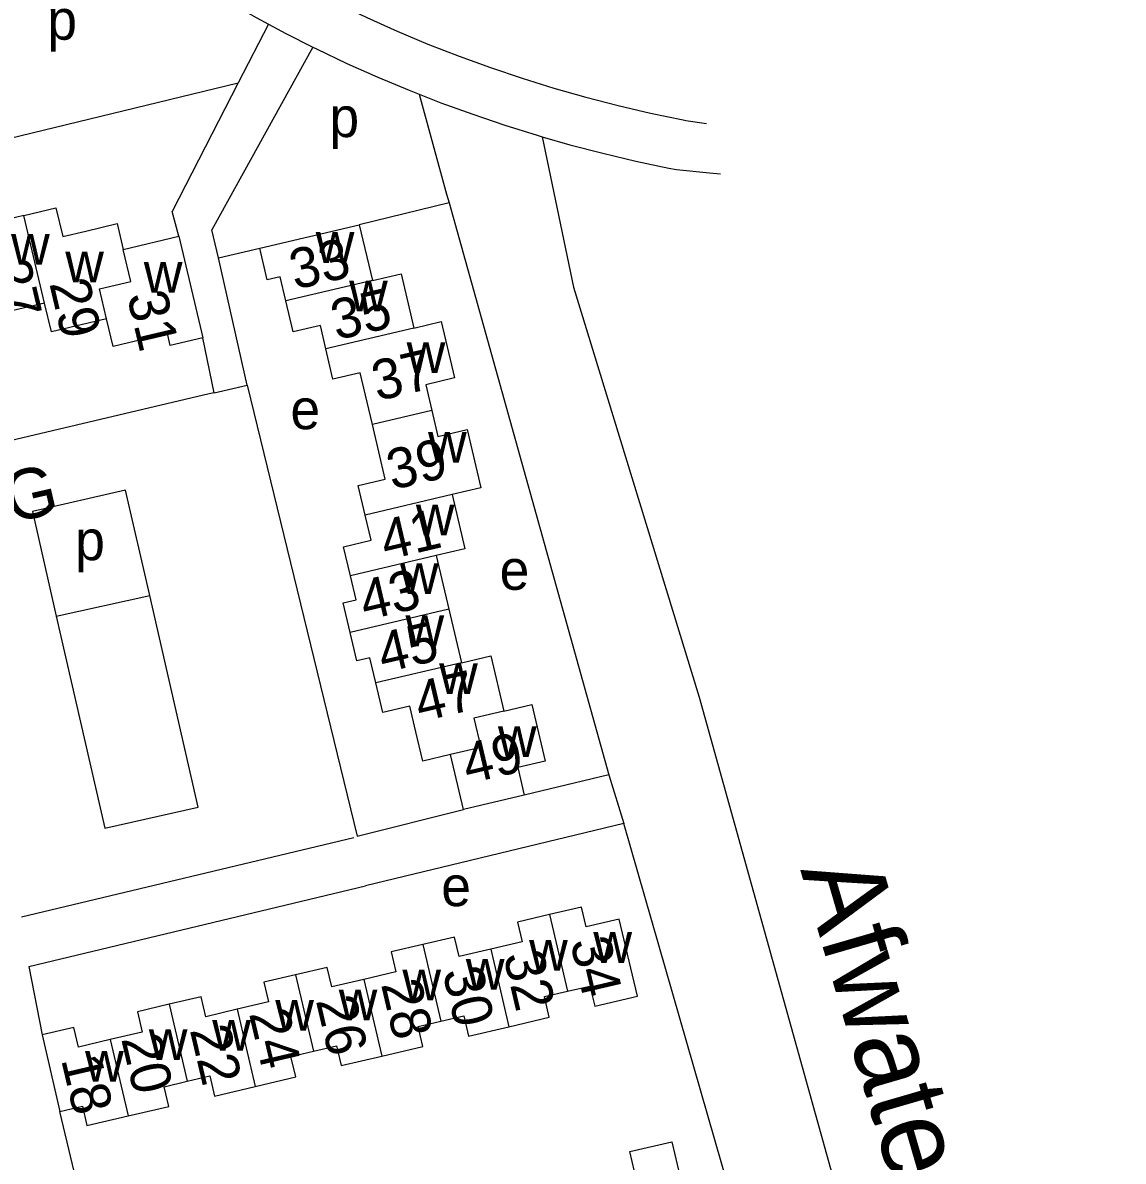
# Model space of a CAD drawing. Extents: x 157646 to 159241, y 379213 to 381217.
# Drawn here: x 159119.4 to 159229.5, y 380620.1 to 380734 of the extents above; entities that cross this region are included whole.
import ezdxf

# ---------------------------------------------------------------- set-up
doc = ezdxf.new("R2010")
doc.units = 0
for name, color, linetype in [('BLT_Basislijn', 7, 'Continuous'), ('BLT_Bebouwing', 7, 'Continuous'), ('BLT_Centroide', 7, 'Continuous'), ('BLT_Huisnummer', 7, 'Continuous'), ('BLT_Huisnummer_ tussenligend', 7, 'Continuous'), ('BLT_Onderverdeling_panden', 7, 'Continuous'), ('BLT_Straatnaam', 7, 'Continuous'), ('BLT_Waternaam_spoorwegen', 7, 'Continuous')]:
    doc.layers.add(name, color=color, linetype=linetype)

msp = doc.modelspace()

# ---------------------------------------------------------------- linework, layer by layer
at = {"layer": 'BLT_Basislijn'}
for p, q in [((159143.95, 380733.82), (159140.92, 380727.95)), ((159148.39, 380731.52), (159138.28, 380713.24)), ((159115.84, 380721.89), (159140.92, 380727.95)), ((159140.92, 380727.95), (159134.29, 380715.08)), ((159162.01, 380715.93), (159153.03, 380713.74)), ((159134.96, 380712.6), (159134.29, 380715.08)), ((159138.93, 380710.45), (159138.28, 380713.24)), ((159138.93, 380710.45), (159143.07, 380711.4)), ((159141.8, 380697.69), (159138.93, 380710.45)), ((159138.5, 380696.95), (159137.36, 380702.45)), ((159138.5, 380696.95), (159141.8, 380697.69)), ((159141.8, 380697.69), (159152.8, 380652.57)), ((159120.32, 380685.07), (159122.71, 380674.59)), ((159122.71, 380674.59), (159132.06, 380676.66)), ((159178.01, 380658.73), (159179.5, 380653.84)), ((159152.8, 380652.57), (159163.44, 380655.25)), ((159119.24, 380644.51), (159152.47, 380652.46)), ((159119.96, 380639.55), (159153.64, 380647.6)), ((159119.96, 380639.55), (159121.29, 380632.7)), ((159127.44, 380606.57), (159123.08, 380625.05))]:
    msp.add_line(p, q, dxfattribs=at)
for points in [[(159128.09, 380749.91), (159130.77, 380747.93), (159133.5, 380746.01), (159136.28, 380744.16), (159139.1, 380742.37), (159141.96, 380740.65), (159144.86, 380739), (159147.79, 380737.43), (159150.77, 380735.92), (159153.78, 380734.48), (159156.83, 380733.12), (159159.9, 380731.83), (159163.01, 380730.61), (159166.14, 380729.47), (159169.31, 380728.41), (159172.49, 380727.42), (159175.7, 380726.51), (159178.93, 380725.67), (159182.18, 380724.91), (159185.44, 380724.23), (159185.71, 380724.18)], [(159122.91, 380747.6), (159125.6, 380745.53), (159128.34, 380743.52), (159131.12, 380741.58), (159133.96, 380739.7), (159136.83, 380737.89), (159139.74, 380736.15), (159142.7, 380734.48), (159143.95, 380733.82)], [(159143.95, 380733.82), (159145.69, 380732.88), (159148.39, 380731.52)], [(159148.39, 380731.52), (159148.73, 380731.35), (159151.79, 380729.89), (159154.89, 380728.51), (159158.02, 380727.2), (159159.01, 380726.81)], [(159159.01, 380726.81), (159161.18, 380725.96), (159164.38, 380724.8), (159167.59, 380723.71), (159170.83, 380722.7), (159171.34, 380722.55)], [(159159.01, 380726.81), (159161.77, 380716.81), (159162.01, 380715.93)], [(159185.71, 380724.18), (159187.78, 380723.88)], [(159171.34, 380722.55), (159174.1, 380721.76), (159177.38, 380720.9), (159180.69, 380720.12), (159184.01, 380719.42), (159184.77, 380719.27)], [(159171.34, 380722.55), (159174.47, 380707.52), (159187.04, 380666.49), (159204.66, 380603.29)], [(159184.77, 380719.27), (159188.07, 380718.94), (159189.17, 380718.86)], [(159162.01, 380715.93), (159178.01, 380658.73)], [(159138.5, 380696.95), (159138.02, 380696.85), (159100, 380687.87), (159047.85, 380675.22)], [(159132.06, 380676.66), (159129.65, 380687.2), (159120.32, 380685.07)], [(159122.71, 380674.59), (159127.56, 380653.37), (159136.89, 380655.5), (159132.06, 380676.66)], [(159178.01, 380658.73), (159169.53, 380656.67)], [(159179.5, 380653.84), (159153.64, 380647.6)], [(159194.21, 380602.73), (159179.5, 380653.84)]]:
    msp.add_lwpolyline(points, dxfattribs=at)
at = {"layer": 'BLT_Bebouwing'}
for p, q in [((159143.07, 380711.4), (159153.03, 380713.74)), ((159153.03, 380713.74), (159154.34, 380708.16)), ((159134.96, 380712.6), (159137.36, 380702.45)), ((159121.54, 380705.91), (159116.22, 380704.66)), ((159160.73, 380680.66), (159161.99, 380675.29)), ((159161.99, 380675.29), (159163.25, 380669.92)), ((159169.53, 380656.67), (159163.44, 380655.25)), ((159121.29, 380632.7), (159123.08, 380625.05))]:
    msp.add_line(p, q, dxfattribs=at)
for points in [[(159119.47, 380714.68), (159122.67, 380715.44), (159123.35, 380712.57), (159125.67, 380713.12)], [(159119.47, 380714.68), (159117.81, 380714.29), (159116.83, 380714.06), (159117.52, 380711.11), (159114.85, 380710.48)], [(159125.67, 380713.12), (159128.81, 380713.86), (159129.41, 380711.29)], [(159129.41, 380711.29), (159134.96, 380712.6)], [(159145.68, 380706.13), (159145.11, 380708.54), (159143.81, 380708.24), (159143.07, 380711.4)], [(159154.34, 380708.16), (159157.21, 380708.84), (159158.48, 380703.42)], [(159127.74, 380704.34), (159122.22, 380703.04), (159121.54, 380705.91)], [(159149.68, 380701.35), (159149.13, 380703.67), (159146.41, 380703.03), (159145.68, 380706.13)], [(159137.36, 380702.45), (159134.11, 380701.68), (159133.84, 380702.86), (159128.39, 380701.57), (159127.74, 380704.34)], [(159158.48, 380703.42), (159161.22, 380704.06), (159162.54, 380698.43), (159159.68, 380697.75), (159160.29, 380695.16)], [(159154.34, 380693.76), (159153.12, 380698.94), (159150.39, 380698.3), (159149.68, 380701.35)], [(159160.29, 380695.16), (159160.9, 380692.58), (159163.81, 380693.26), (159165.18, 380687.42), (159162.33, 380686.76)], [(159153.61, 380684.71), (159152.92, 380687.66), (159155.62, 380688.29), (159154.34, 380693.76)], [(159162.33, 380686.76), (159163.6, 380681.33), (159160.73, 380680.66)], [(159152.15, 380678.64), (159151.46, 380681.54), (159154.21, 380682.19), (159153.61, 380684.71)], [(159152.11, 380672.97), (159151.42, 380675.93), (159152.71, 380676.23), (159152.15, 380678.64)], [(159154.69, 380667.91), (159154.09, 380670.44), (159152.78, 380670.13), (159152.11, 380672.97)], [(159163.25, 380669.92), (159166.18, 380670.61), (159167.48, 380665.08)], [(159158.7, 380663.02), (159158.09, 380665.59), (159155.38, 380664.96), (159154.69, 380667.91)], [(159167.48, 380665.08), (159170.3, 380665.74), (159171.63, 380660.09), (159168.88, 380659.44), (159169.53, 380656.67)], [(159162.16, 380660.75), (159159.39, 380660.1), (159158.7, 380663.02)], [(159163.44, 380655.25), (159162.16, 380660.75)], [(159173.85, 380637.06), (159176.11, 380637.59), (159176.59, 380635.56), (159180.85, 380636.56), (159179.04, 380644.28), (159175.72, 380643.5), (159175.25, 380645.49), (159172.05, 380644.74)], [(159172.05, 380644.74), (159168.85, 380643.99), (159169.32, 380642), (159166.18, 380641.27)], [(159166.18, 380641.27), (159163.03, 380640.53), (159162.57, 380642.49), (159159.39, 380641.74)], [(159159.39, 380641.74), (159156.21, 380641), (159156.68, 380639), (159153.49, 380638.25)], [(159153.49, 380638.25), (159150.29, 380637.5), (159149.83, 380639.46), (159146.66, 380638.72)], [(159146.66, 380638.72), (159143.49, 380637.98), (159143.95, 380636), (159140.81, 380635.26)], [(159167.99, 380633.52), (159172.04, 380634.47), (159171.56, 380636.53), (159173.85, 380637.06)], [(159134.01, 380635.77), (159130.83, 380635.02), (159131.3, 380632.98), (159128.11, 380632.23)], [(159140.81, 380635.26), (159137.66, 380634.52), (159137.19, 380636.51), (159134.01, 380635.77)], [(159161.19, 380634.08), (159163.49, 380634.62), (159163.97, 380632.58), (159167.99, 380633.52)], [(159128.11, 380632.23), (159124.93, 380631.48), (159124.46, 380633.45), (159121.29, 380632.7)], [(159155.28, 380630.58), (159159.4, 380631.55), (159158.93, 380633.55), (159161.19, 380634.08)], [(159148.45, 380631.08), (159150.75, 380631.62), (159151.22, 380629.63), (159155.28, 380630.58)], [(159142.62, 380627.54), (159146.67, 380628.49), (159146.18, 380630.55), (159148.45, 380631.08)], [(159129.9, 380624.6), (159130.65, 380624.77), (159133.97, 380625.55), (159133.51, 380627.52), (159135.82, 380628.06)], [(159135.82, 380628.06), (159138.07, 380628.59), (159138.54, 380626.58), (159142.62, 380627.54)], [(159123.08, 380625.05), (159125.32, 380625.58), (159125.78, 380623.63), (159129.9, 380624.6)], [(159178.27, 380618.49), (159180.57, 380619.03), (159180.1, 380621.03), (159184.3, 380622.01), (159186.13, 380614.21), (159182.84, 380613.43), (159183.3, 380611.48), (159180.09, 380610.73)]]:
    msp.add_lwpolyline(points, dxfattribs=at)
at = {"layer": 'BLT_Onderverdeling_panden'}
for p, q in [((159121.54, 380705.91), (159119.47, 380714.68)), ((159154.34, 380708.16), (159145.68, 380706.13)), ((159158.48, 380703.42), (159149.68, 380701.35)), ((159160.29, 380695.16), (159154.34, 380693.76)), ((159162.33, 380686.76), (159153.61, 380684.71)), ((159160.73, 380680.66), (159152.15, 380678.64)), ((159161.99, 380675.29), (159152.11, 380672.97)), ((159163.25, 380669.92), (159154.69, 380667.91)), ((159172.05, 380644.74), (159173.85, 380637.06)), ((159159.39, 380641.74), (159161.19, 380634.08)), ((159166.18, 380641.27), (159167.99, 380633.52)), ((159146.66, 380638.72), (159148.45, 380631.08)), ((159153.49, 380638.25), (159155.28, 380630.58)), ((159134.01, 380635.77), (159135.82, 380628.06)), ((159140.81, 380635.26), (159142.62, 380627.54)), ((159128.11, 380632.23), (159129.9, 380624.6))]:
    msp.add_line(p, q, dxfattribs=at)
for points in [[(159127.74, 380704.34), (159127.03, 380707.34), (159130.17, 380708.08), (159129.41, 380711.29)], [(159167.48, 380665.08), (159164.5, 380664.38), (159165.18, 380661.46), (159162.16, 380660.75)]]:
    msp.add_lwpolyline(points, dxfattribs=at)

# ---------------------------------------------------------------- texts
at = {"layer": 'BLT_Centroide'}
for s, p in [('p', (159121.81, 380732.26)), ('p', (159150.04, 380722.52)), ('w', (159118.19, 380709.75)), ('w', (159148.67, 380709.94)), ('w', (159123.61, 380708)), ('w', (159131.47, 380706.94)), ('w', (159152.01, 380705.09)), ('w', (159157.77, 380698.91)), ('e', (159146.14, 380693.3)), ('w', (159159.91, 380689.94)), ('w', (159158.69, 380682.69)), ('p', (159124.6, 380680.19)), ('e', (159167.07, 380677.23)), ('w', (159157.1, 380676.81)), ('w', (159157.65, 380671.59)), ('w', (159161.02, 380666.81)), ('w', (159166.9, 380660.5)), ('e', (159161.23, 380645.58)), ('w', (159176.45, 380639.91)), ('w', (159170.02, 380639.12)), ('w', (159163.69, 380637.22)), ('w', (159157.34, 380636.16)), ('w', (159150.97, 380634.17)), ('w', (159144.62, 380633.12)), ('w', (159138.31, 380631.12)), ('w', (159131.97, 380630.19)), ('w', (159125.59, 380628.02))]:
    msp.add_text(s, height=4, dxfattribs=at).set_placement(p)
at = {"layer": 'BLT_Huisnummer'}
for s, rotation, p in [('33', 13.2172, (159146.59, 380707.24)), ('31', 283.2936, (159129.76, 380706.66)), ('37', 13.2172, (159154.83, 380696.1)), ('41', 13.2172, (159155.68, 380680.17)), ('45', 13.2172, (159155.42, 380668.89)), ('49', 13.2172, (159163.89, 380657.8)), ('34', 283.2051, (159174.11, 380642.03)), ('30', 283.2051, (159161.34, 380639.03)), ('26', 283.2051, (159148.67, 380636.15)), ('22', 283.2161, (159136.06, 380633.21)), ('18', 283.1964, (159123.18, 380630.25))]:
    msp.add_text(s, height=4, rotation=rotation, dxfattribs=at).set_placement(p)
at = {"layer": 'BLT_Huisnummer_ tussenligend'}
for s, rotation, p in [('27', 283.2773, (159116.07, 380709.82)), ('29', 283.2773, (159122, 380707.89)), ('35', 13.2172, (159150.74, 380702.19)), ('39', 13.2172, (159156.32, 380687.21)), ('43', 13.2172, (159153.61, 380674.14)), ('47', 13.2172, (159159.11, 380663.99)), ('32', 283.2051, (159167.42, 380640.65)), ('28', 283.2051, (159155.19, 380637.78)), ('24', 283.2161, (159141.98, 380634.85)), ('20', 283.1964, (159129.19, 380632.32))]:
    msp.add_text(s, height=4, rotation=rotation, dxfattribs=at).set_placement(p)
at = {"layer": 'BLT_Straatnaam'}
msp.add_text('ENNEMABORG', height=5, rotation=12.8997, dxfattribs=at).set_placement((159076.14, 380674.25))
at = {"layer": 'BLT_Waternaam_spoorwegen'}
msp.add_text('Afwateringskanaal', height=7.9999, rotation=286.2296, dxfattribs=at).set_placement((159197.14, 380649.23))

doc.saveas('drawing.dxf')
